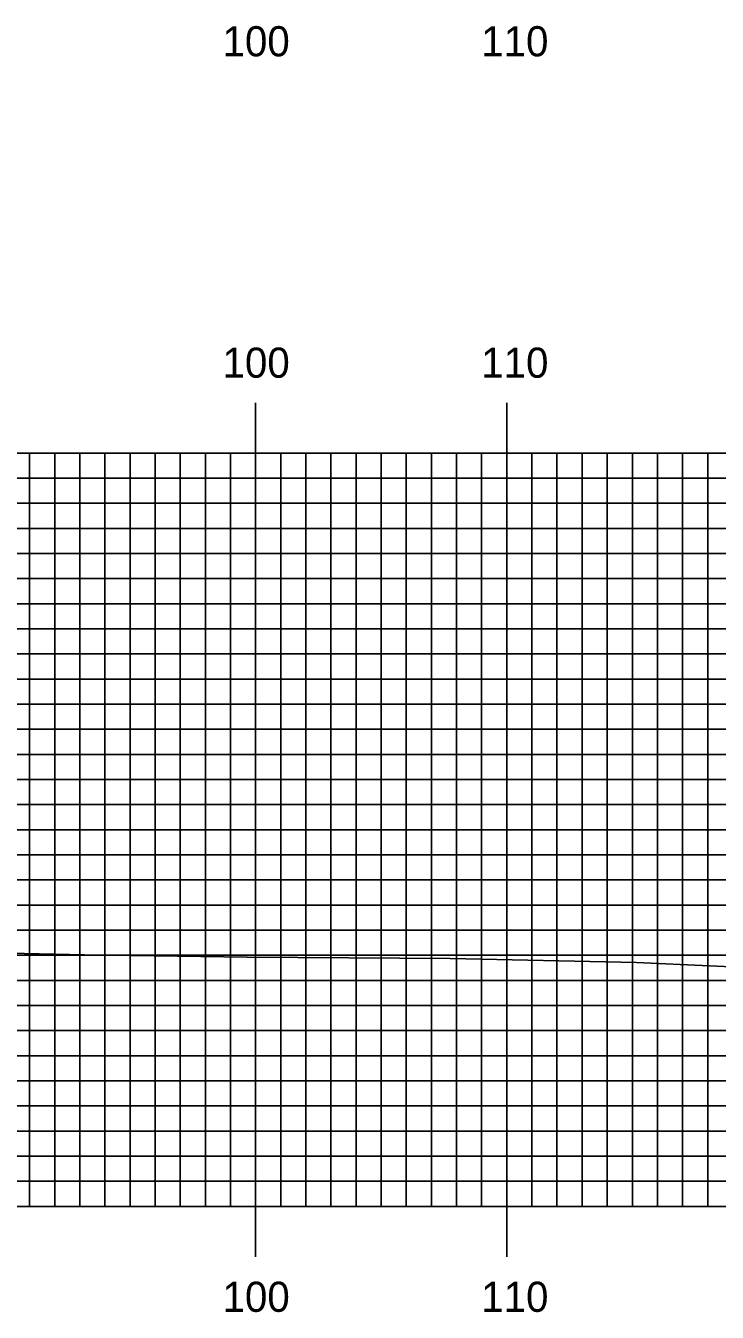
# Model space of a CAD drawing. Extents: x 1807832 to 1808175, y 442591 to 442811.
# Drawn here: x 1808088.6 to 1808116.2, y 442704.4 to 442755.7 of the extents above; entities that cross this region are included whole.
import ezdxf

# ---------------------------------------------------------------- set-up
doc = ezdxf.new("R2010")
doc.units = 0
for name, color, linetype in [('H_V ANNOTATION', 7, 'Continuous'), ('MAJOR', 7, 'Continuous'), ('MINOR', 7, 'Continuous'), ('S_Roadway_Centerline', 7, 'Continuous')]:
    doc.layers.add(name, color=color, linetype=linetype)

msp = doc.modelspace()

# ---------------------------------------------------------------- linework, layer by layer
at = {"layer": 'MAJOR'}
for p, q in [((1808097.785, 442740.669), (1808097.785, 442738.665)), ((1808107.785, 442740.669), (1808107.785, 442738.665)), ((1807857.785, 442738.665), (1808137.785, 442738.665)), ((1807857.785, 442738.665), (1808137.785, 442738.665)), ((1808097.785, 442708.665), (1808097.785, 442738.665)), ((1808107.785, 442708.665), (1808107.785, 442738.665)), ((1807857.785, 442733.665), (1808137.785, 442733.665)), ((1807857.785, 442728.665), (1808137.785, 442728.665)), ((1807857.785, 442723.665), (1808137.785, 442723.665)), ((1807857.785, 442718.665), (1808137.785, 442718.665)), ((1807857.785, 442713.665), (1808137.785, 442713.665)), ((1807857.785, 442708.665), (1808137.785, 442708.665)), ((1807857.785, 442708.665), (1808137.785, 442708.665)), ((1808097.785, 442706.661), (1808097.785, 442708.665)), ((1808107.785, 442706.661), (1808107.785, 442708.665))]:
    msp.add_line(p, q, dxfattribs=at)
at = {"layer": 'MINOR'}
for p, q in [((1808088.785, 442708.665), (1808088.785, 442738.665)), ((1808089.785, 442708.665), (1808089.785, 442738.665)), ((1808090.785, 442708.665), (1808090.785, 442738.665)), ((1808091.785, 442708.665), (1808091.785, 442738.665)), ((1808092.785, 442708.665), (1808092.785, 442738.665)), ((1808093.785, 442708.665), (1808093.785, 442738.665)), ((1808094.785, 442708.665), (1808094.785, 442738.665)), ((1808095.785, 442708.665), (1808095.785, 442738.665)), ((1808096.785, 442708.665), (1808096.785, 442738.665)), ((1808098.785, 442708.665), (1808098.785, 442738.665)), ((1808099.785, 442708.665), (1808099.785, 442738.665)), ((1808100.785, 442708.665), (1808100.785, 442738.665)), ((1808101.785, 442708.665), (1808101.785, 442738.665)), ((1808102.785, 442708.665), (1808102.785, 442738.665)), ((1808103.785, 442708.665), (1808103.785, 442738.665)), ((1808104.785, 442708.665), (1808104.785, 442738.665)), ((1808105.785, 442708.665), (1808105.785, 442738.665)), ((1808106.785, 442708.665), (1808106.785, 442738.665)), ((1808108.785, 442708.665), (1808108.785, 442738.665)), ((1808109.785, 442708.665), (1808109.785, 442738.665)), ((1808110.785, 442708.665), (1808110.785, 442738.665)), ((1808111.785, 442708.665), (1808111.785, 442738.665)), ((1808112.785, 442708.665), (1808112.785, 442738.665)), ((1808113.785, 442708.665), (1808113.785, 442738.665)), ((1808114.785, 442708.665), (1808114.785, 442738.665)), ((1808115.785, 442708.665), (1808115.785, 442738.665)), ((1807857.785, 442737.665), (1808137.785, 442737.665)), ((1807857.785, 442736.665), (1808137.785, 442736.665)), ((1807857.785, 442735.665), (1808137.785, 442735.665)), ((1807857.785, 442734.665), (1808137.785, 442734.665)), ((1807857.785, 442732.665), (1808137.785, 442732.665)), ((1807857.785, 442731.665), (1808137.785, 442731.665)), ((1807857.785, 442730.665), (1808137.785, 442730.665)), ((1807857.785, 442729.665), (1808137.785, 442729.665)), ((1807857.785, 442727.665), (1808137.785, 442727.665)), ((1807857.785, 442726.665), (1808137.785, 442726.665)), ((1807857.785, 442725.665), (1808137.785, 442725.665)), ((1807857.785, 442724.665), (1808137.785, 442724.665)), ((1807857.785, 442722.665), (1808137.785, 442722.665)), ((1807857.785, 442721.665), (1808137.785, 442721.665)), ((1807857.785, 442720.665), (1808137.785, 442720.665)), ((1807857.785, 442719.665), (1808137.785, 442719.665)), ((1807857.785, 442717.665), (1808137.785, 442717.665)), ((1807857.785, 442716.665), (1808137.785, 442716.665)), ((1807857.785, 442715.665), (1808137.785, 442715.665)), ((1807857.785, 442714.665), (1808137.785, 442714.665)), ((1807857.785, 442712.665), (1808137.785, 442712.665)), ((1807857.785, 442711.665), (1808137.785, 442711.665)), ((1807857.785, 442710.665), (1808137.785, 442710.665)), ((1807857.785, 442709.665), (1808137.785, 442709.665))]:
    msp.add_line(p, q, dxfattribs=at)
at = {"layer": 'S_Roadway_Centerline'}
msp.add_lwpolyline([(1808048.448, 442720.043), (1808059.943, 442719.833), (1808068.47, 442719.682), (1808070.712, 442719.592), (1808081.958, 442718.876), (1808090.973, 442718.68), (1808097.443, 442718.589), (1808105.538, 442718.533), (1808112.951, 442718.382), (1808121.669, 442717.984), (1808133.631, 442717.501), (1808137.785, 442717.407)], dxfattribs=at)

# ---------------------------------------------------------------- texts
at = {"layer": 'H_V ANNOTATION'}
for s, p in [('100', (1808096.468, 442754.465)), ('110', (1808106.768, 442754.465)), ('100', (1808096.468, 442741.665)), ('110', (1808106.768, 442741.665)), ('100', (1808096.468, 442704.465)), ('110', (1808106.768, 442704.465))]:
    msp.add_text(s, height=1.2, dxfattribs=at).set_placement(p)

doc.saveas('drawing.dxf')
